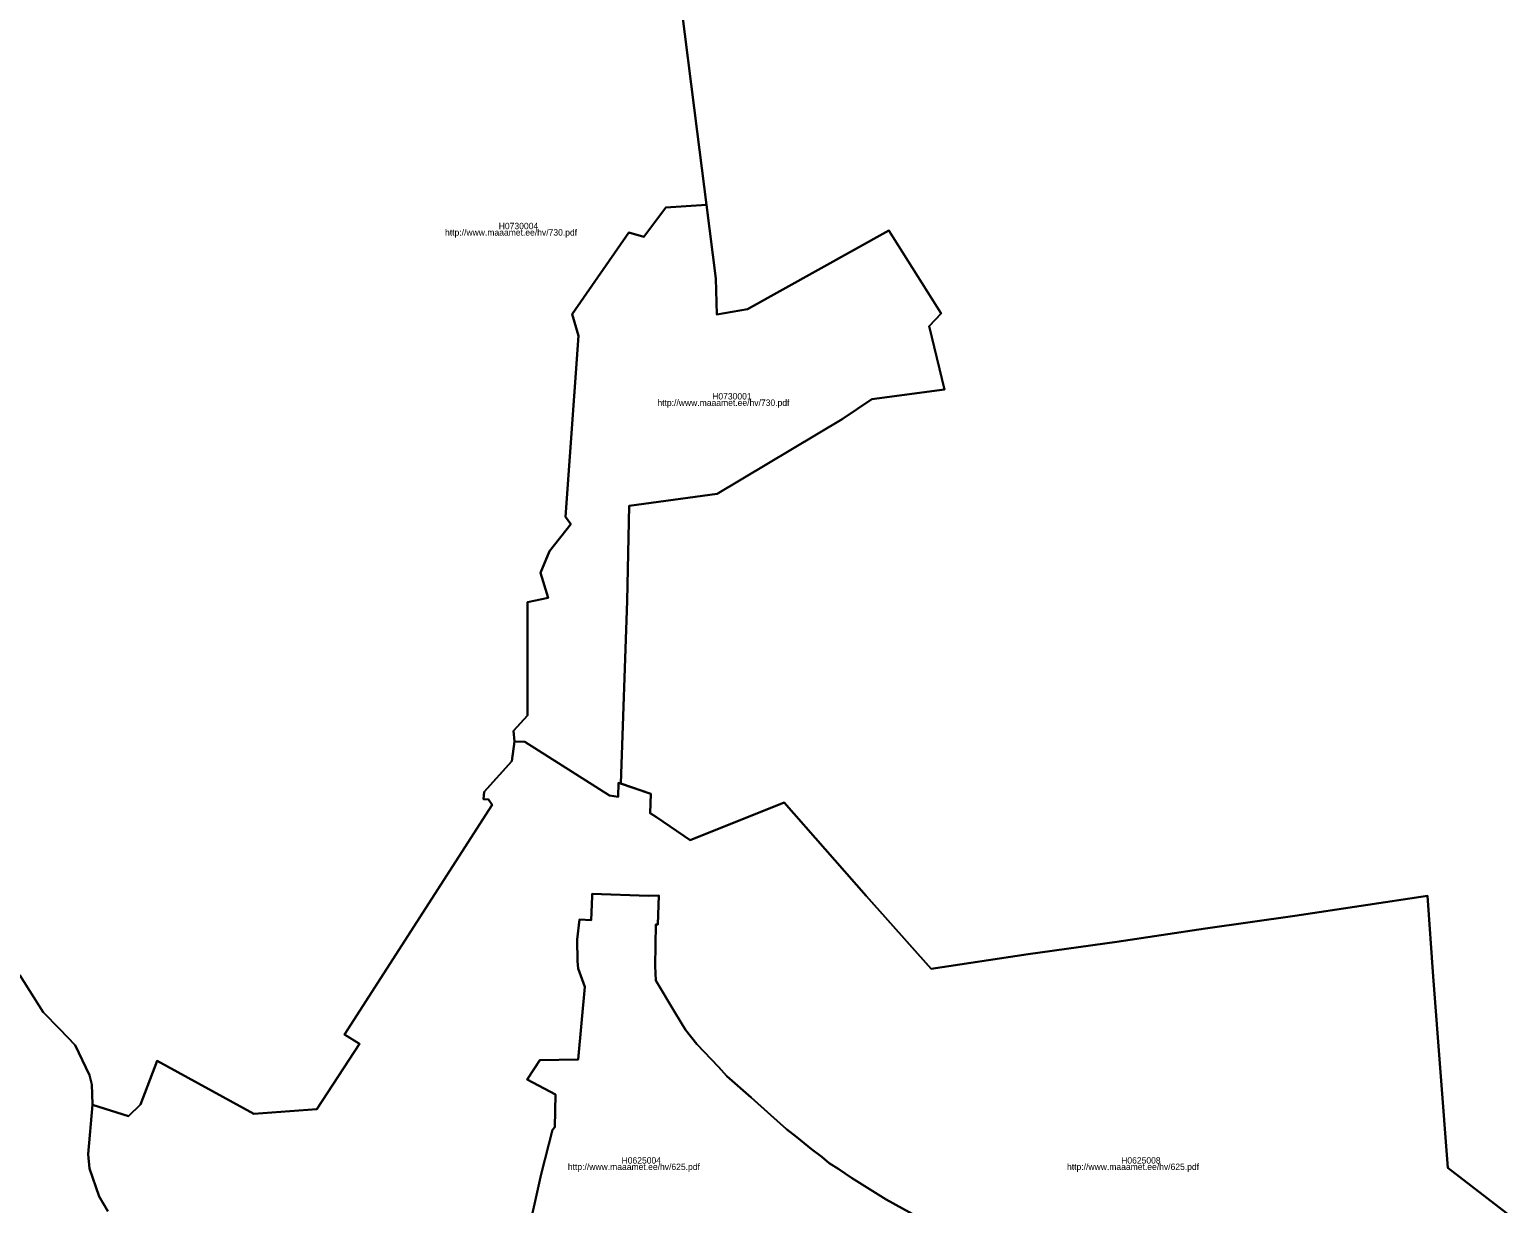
# Model space of a CAD drawing. Extents: x 369010 to 739155, y 6377141 to 6634081.
# Drawn here: x 526588 to 532381, y 6473413 to 6478005 of the extents above; entities that cross this region are included whole.
import ezdxf

# ---------------------------------------------------------------- set-up
doc = ezdxf.new("R2010")
doc.units = 0
for name, color, linetype in [('H_LINK', 7, 'Continuous'), ('H_PIIR', 7, 'Continuous'), ('H_TUNNUS', 7, 'Continuous')]:
    doc.layers.add(name, color=color, linetype=linetype)

msp = doc.modelspace()

# ---------------------------------------------------------------- linework, layer by layer
at = {"layer": 'H_PIIR'}
for points in [[(529127.71, 6478173.4699), (529200.11, 6477606.78), (529236.2999, 6477319.28), (529076.5601, 6477309.8601), (528991.38, 6477194.81), (528931.7601, 6477211.86), (528710.31, 6476892.29), (528735.86, 6476807.07), (528684.7501, 6476099.7699), (528706.0499, 6476069.9401), (528621.55, 6475965.4199), (528587.48, 6475880.21), (528617.2901, 6475782.21), (528536.3799, 6475765.1599), (528536.3799, 6475322.0299), (528481.0099, 6475262.38), (528485.5205, 6475219.6655), (528485.25, 6475219.67), (528474.89, 6475142.93), (528365.92, 6475022.7301), (528364.5099, 6474994.4901), (528383.73, 6474993.8801), (528398.36, 6474972.83), (527820.05, 6474073.71), (527878.34, 6474036.9), (527712.4999, 6473781.6401), (527465.24, 6473763.5899), (527087.83, 6473970.9001), (527021.64, 6473800.17), (526975.34, 6473754.4701), (526833.94, 6473798.8299), (526834.14, 6473801.2801), (526832.3, 6473878.0101), (526822.56, 6473914.2901), (526766.54, 6474032.24), (526705.37, 6474095.63), (526640.92, 6474161.7799), (526549.8499, 6474306.46)], [(532380.8399, 6473363), (532136.3301, 6473552.5401), (532078.79, 6474301.4099), (532056.8, 6474616.19), (531537.2999, 6474538.34), (531187.87, 6474488.4201), (530840.9801, 6474436.8), (530494.94, 6474387.72), (530115.0399, 6474331.03), (529860.38, 6474616.2), (529540.56, 6474981.7401), (529172.51, 6474833.66), (529041.1899, 6474924.14), (529015.2599, 6474939.5399), (529017.95, 6475015.38), (528900.66, 6475055.6213), (528926.36, 6475770.28), (528933.4801, 6476141.9399), (529277.65, 6476189.4401), (529766.6101, 6476481.54), (529882.91, 6476559.91), (530167.1201, 6476597.51), (530107.17, 6476845.4201), (530154.07, 6476895.21), (529949.65, 6477219.04), (529396.01, 6476912.2499), (529276.7701, 6476890.9501), (529272.51, 6477031.56), (529236.2999, 6477319.28), (529200.11, 6477606.78), (529127.71, 6478173.4699)], [(526894.58, 6473382.58), (526859.94, 6473440.0801), (526822.3501, 6473549.18), (526817.93, 6473605.2), (526833.94, 6473798.8299), (526975.34, 6473754.4701), (527021.64, 6473800.17), (527087.83, 6473970.9001), (527465.24, 6473763.5899), (527712.4999, 6473781.6401), (527878.34, 6474036.9), (527820.05, 6474073.71), (528398.36, 6474972.83), (528383.73, 6474993.8801), (528364.5099, 6474994.4901), (528365.92, 6475022.7301), (528474.89, 6475142.93), (528485.25, 6475219.67), (528525.11, 6475219.02), (528856.87, 6475009.3699), (528890.1199, 6475004.37), (528891.9201, 6475058.62), (529017.95, 6475015.38), (529015.2599, 6474939.5399), (529041.1899, 6474924.14), (529172.51, 6474833.66), (529540.56, 6474981.7401), (529860.38, 6474616.2), (530115.0399, 6474331.03), (530494.94, 6474387.72), (530840.9801, 6474436.8), (531187.87, 6474488.4201), (531537.2999, 6474538.34), (532056.8, 6474616.19), (532078.79, 6474301.4099), (532136.3301, 6473552.5401), (532380.8399, 6473363)], [(530156.6701, 6473307.9101), (529939.2001, 6473428.33), (529802.78, 6473512.6199), (529753.7999, 6473546.55), (529715.55, 6473570.4601), (529686.73, 6473594.83), (529647.51, 6473625.6899), (529589.4901, 6473671.7), (529548.83, 6473703.0799), (529488.4299, 6473757.8499), (529411.1099, 6473827.56), (529316.27, 6473910.5), (529282.78, 6473946.86), (529197.8, 6474036.4899), (529154.66, 6474091.8899), (529113.5101, 6474158.48), (529038.02, 6474285.2399), (529035.0301, 6474342.05), (529037.48, 6474504.67), (529046.24, 6474504.29), (529050.14, 6474618.2101), (529009.8, 6474616.9799), (528788.6001, 6474624.89), (528788.98, 6474614.1701), (528784.98, 6474521.52), (528739.0001, 6474523.38), (528729.8601, 6474445.7301), (528731.89, 6474361.4199), (528734.2, 6474332.19), (528759.98, 6474260.6), (528733.7699, 6473975.85), (528583.7199, 6473973.95), (528534.7099, 6473898.57), (528645.3899, 6473839.53), (528642.5699, 6473711.7199), (528633.61, 6473700.38), (528589.67, 6473527.89), (528530.48, 6473264.36)], [(528530.48, 6473264.36), (528589.67, 6473527.89), (528633.61, 6473700.38), (528642.5699, 6473711.7199), (528645.3899, 6473839.53), (528534.7099, 6473898.57), (528583.7199, 6473973.95), (528733.7699, 6473975.85), (528759.98, 6474260.6), (528734.2, 6474332.19), (528731.89, 6474361.4199), (528729.8601, 6474445.7301), (528739.0001, 6474523.38), (528784.98, 6474521.52), (528788.98, 6474614.1701), (528788.6001, 6474624.89), (529009.8, 6474616.9799), (529050.14, 6474618.2101), (529046.24, 6474504.29), (529037.48, 6474504.67), (529035.0301, 6474342.05), (529038.02, 6474285.2399), (529113.5101, 6474158.48), (529154.66, 6474091.8899), (529197.8, 6474036.4899), (529282.78, 6473946.86), (529316.27, 6473910.5), (529411.1099, 6473827.56), (529488.4299, 6473757.8499), (529548.83, 6473703.0799), (529589.4901, 6473671.7), (529647.51, 6473625.6899), (529686.73, 6473594.83), (529715.55, 6473570.4601), (529753.7999, 6473546.55), (529802.78, 6473512.6199), (529939.2001, 6473428.33), (530156.6701, 6473307.9101)], [(526549.8499, 6474306.46), (526640.92, 6474161.7799), (526705.37, 6474095.63), (526766.54, 6474032.24), (526822.56, 6473914.2901), (526832.3, 6473878.0101), (526834.14, 6473801.2801), (526833.94, 6473798.8299), (526817.93, 6473605.2), (526822.3501, 6473549.18), (526859.94, 6473440.0801), (526894.58, 6473382.58)]]:
    msp.add_lwpolyline(points, dxfattribs=at)
msp.add_lwpolyline([(529236.2999, 6477319.28), (529272.51, 6477031.56), (529276.7701, 6476890.9501), (529396.01, 6476912.2499), (529949.65, 6477219.04), (530154.07, 6476895.21), (530107.17, 6476845.4201), (530167.1201, 6476597.51), (529882.91, 6476559.91), (529766.6101, 6476481.54), (529277.65, 6476189.4401), (528933.4801, 6476141.9399), (528926.36, 6475770.28), (528900.66, 6475055.6213), (528891.9201, 6475058.62), (528890.1199, 6475004.37), (528856.87, 6475009.3699), (528525.11, 6475219.02), (528485.52, 6475219.67), (528481.0099, 6475262.38), (528536.3799, 6475322.0299), (528536.3799, 6475765.1599), (528617.2901, 6475782.21), (528587.48, 6475880.21), (528621.55, 6475965.4199), (528706.0499, 6476069.9401), (528684.7501, 6476099.7699), (528735.86, 6476807.07), (528710.31, 6476892.29), (528931.7601, 6477211.86), (528991.38, 6477194.81), (529076.5601, 6477309.8601)], close=True, dxfattribs=at)

# ---------------------------------------------------------------- texts
at = {"layer": 'H_LINK'}
for s, p in [('http://www.maaamet.ee/hv/730.pdf', (528213.4306, 6477199.5098)), ('http://www.maaamet.ee/hv/730.pdf', (529044.0906, 6476533.2832)), ('http://www.maaamet.ee/hv/625.pdf', (530646.4677, 6473544.0399))]:
    msp.add_text(s, height=25, rotation=0, dxfattribs=at).set_placement(p)
msp.add_text('http://www.maaamet.ee/hv/625.pdf', height=25, dxfattribs=at).set_placement((528693.9007, 6473543.9406))
at = {"layer": 'H_TUNNUS'}
for s, p in [('H0730004', (528423.4099, 6477224.5098)), ('H0730001', (529258.4446, 6476558.2832)), ('H0625008', (530858.3223, 6473569.0399))]:
    msp.add_text(s, height=25, rotation=0, dxfattribs=at).set_placement(p)
msp.add_text('H0625004', height=25, dxfattribs=at).set_placement((528903.88, 6473568.9406))

doc.saveas('drawing.dxf')
